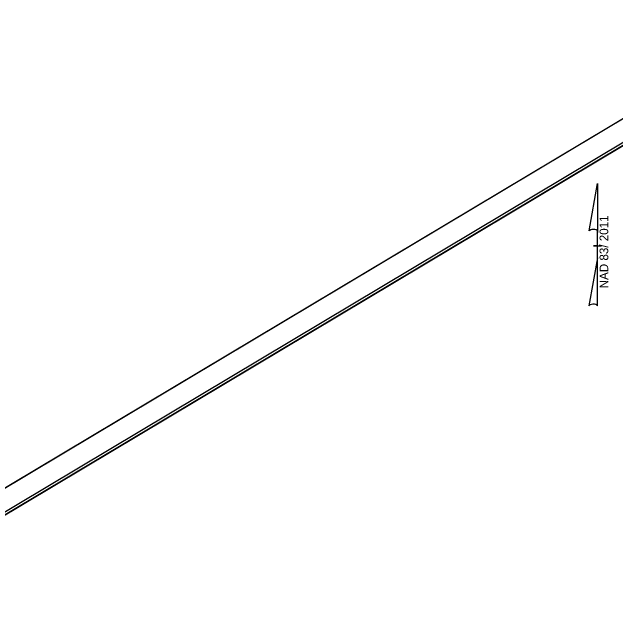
# Model space of a CAD drawing. Extents: x 1487794 to 1489801, y 498102 to 499906.
# Drawn here: x 1488466 to 1489058, y 499304 to 499906 of the extents above; entities that cross this region are included whole.
import ezdxf

# ---------------------------------------------------------------- set-up
doc = ezdxf.new("R2010")
doc.units = 0
for name, color, linetype in [('Exist Vertical Profile Ground Line', 7, 'Continuous'), ('Exist Vertical Profile Horizontal Axis Label Major', 7, 'Continuous'), ('Exist Vertical Profile Vertical Axis Label', 7, 'Continuous'), ('Prop Terminator CELL', 7, 'Continuous'), ('Prop VPI Label', 7, 'Continuous'), ('Sheet Profile Grid Middle CELL', 7, 'Continuous')]:
    doc.layers.add(name, color=color, linetype=linetype)

msp = doc.modelspace()

# ---------------------------------------------------------------- linework, layer by layer
at = {"layer": 'Exist Vertical Profile Ground Line'}
msp.add_lwpolyline([(1488356.6, 498126.17), (1489787.01, 498980.28), (1489246.14, 499886.09), (1487815.74, 499031.98)], close=True, dxfattribs=at)
at = {"layer": 'Exist Vertical Profile Horizontal Axis Label Major'}
msp.add_lwpolyline([(1488355.69, 498102.34), (1489801.12, 498965.41), (1489239.75, 499905.57), (1487794.32, 499042.49)], close=True, dxfattribs=at)
at = {"layer": 'Exist Vertical Profile Vertical Axis Label'}
msp.add_line((1489239.75, 499905.57), (1487794.32, 499042.49), dxfattribs=at)
at = {"layer": 'Prop Terminator CELL'}
msp.add_lwpolyline([(1488230.78, 498636.31), (1487948.81, 499108.53), (1489064.93, 499774.97), (1489153.91, 499625.97), (1489135.02, 499614.69), (1489151.4, 499587.25), (1489342.04, 499701.08), (1489518.66, 499405.31)], close=True, dxfattribs=at)
at = {"layer": 'Prop VPI Label'}
for p, q in [((1489031.66, 499691.33), (1489039.88, 499737.68)), ((1489039.93, 499737.68), (1489039.88, 499737.68)), ((1489039.93, 499737.68), (1489039.88, 499737.68)), ((1489039.93, 499737.68), (1489039.91, 499689.88)), ((1489039.9, 499665.08), (1489039.91, 499691.28)), ((1489039.91, 499689.88), (1489039.91, 499691.23)), ((1489035.9, 499676.68), (1489035.85, 499676.68)), ((1489039.45, 499676.68), (1489035.9, 499676.68)), ((1489035.95, 499676.68), (1489043.95, 499676.67)), ((1489039.9, 499665.08), (1489031.53, 499617.83)), ((1489039.93, 499618.03), (1489039.9, 499665.08))]:
    msp.add_line(p, q, dxfattribs=at)
for centre, start_param, end_param in [((1489035.8, 499690.83), 0.216388, 2.908219), ((1489035.76, 499617.66), 0.201328, 3.141593)]:
    msp.add_ellipse(centre, major_axis=(4.23, -0.03), ratio=0.461098, start_param=start_param, end_param=end_param, dxfattribs=at)
at = {"layer": 'Sheet Profile Grid Middle CELL'}
msp.add_lwpolyline([(1489236.69, 499877.53), (1487948.81, 499108.53), (1488487.11, 498207.01), (1489774.99, 498976.02)], close=True, dxfattribs=at)

# ---------------------------------------------------------------- texts
at = {"layer": 'Prop VPI Label'}
msp.add_text('NAD 83/ 2011', height=8.5, rotation=89.97606, dxfattribs=at).set_placement((1489050.41, 499635.15))

doc.saveas('drawing.dxf')
